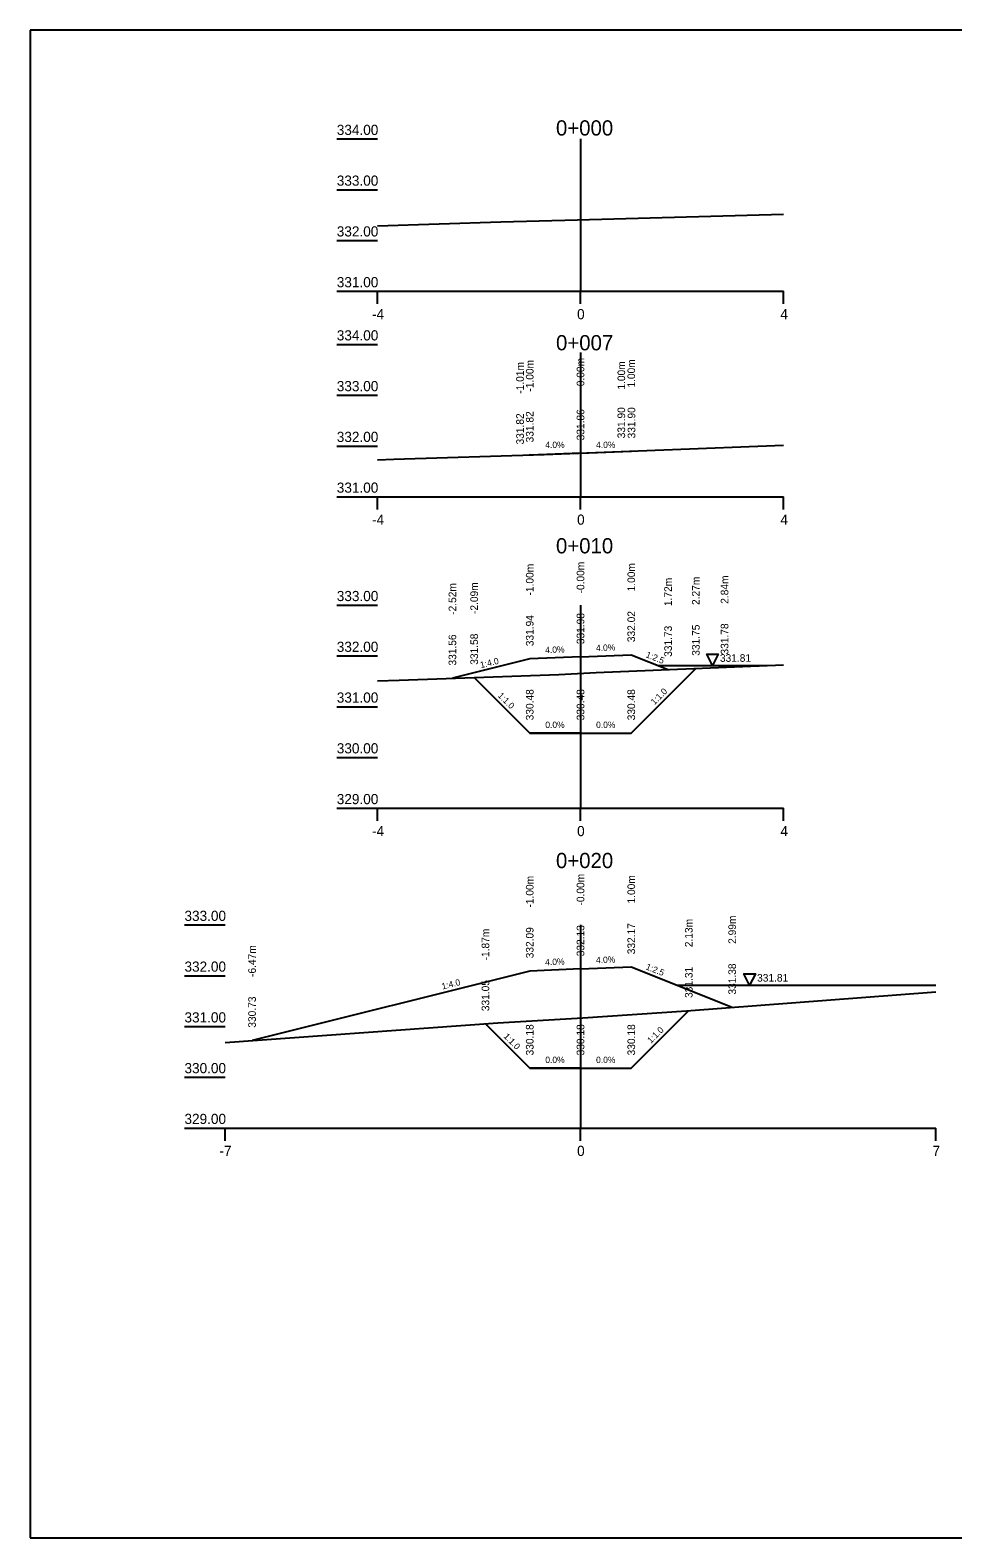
# Model space of a CAD drawing. Extents: x -560471.6 to -560429.6, y -1163651 to -1163621.3.
# Drawn here: x -560471.64 to -560453.47, y -1163650.97 to -1163621.27 of the extents above; entities that cross this region are included whole.
import ezdxf

# ---------------------------------------------------------------- set-up
doc = ezdxf.new("R2010")
doc.units = 0
for name, color, linetype in [('16', 7, 'Continuous'), ('21', 7, 'Continuous'), ('28', 7, 'Continuous'), ('59', 7, 'Continuous'), ('Body pricny rez', 7, 'Continuous'), ('Popis pricneho profilu', 7, 'Continuous')]:
    doc.layers.add(name, color=color, linetype=linetype)

msp = doc.modelspace()

# ---------------------------------------------------------------- linework, layer by layer
for p, q in [((-560429.645, -1163621.275), (-560471.645, -1163621.275)), ((-560471.645, -1163621.275), (-560471.645, -1163650.975)), ((-560471.645, -1163650.975), (-560429.645, -1163650.975))]:
    msp.add_line(p, q)
for points in [[(-560464.805, -1163625.129), (-560462.376, -1163625.054), (-560460.867, -1163625.01), (-560456.805, -1163624.899)], [(-560464.805, -1163629.74), (-560464.481, -1163629.729), (-560461.518, -1163629.633), (-560456.805, -1163629.453)], [(-560461.805, -1163629.646), (-560461.82, -1163629.643)], [(-560460.805, -1163629.606), (-560461.805, -1163629.646)], [(-560460.805, -1163629.606), (-560459.805, -1163629.566)], [(-560459.805, -1163629.566), (-560459.801, -1163629.567)], [(-560464.805, -1163634.095), (-560464.379, -1163634.08), (-560461.23, -1163633.965), (-560460.499, -1163633.93), (-560456.805, -1163633.777)], [(-560461.805, -1163633.661), (-560463.328, -1163634.042)], [(-560460.805, -1163633.621), (-560461.805, -1163633.661)], [(-560460.805, -1163633.621), (-560459.805, -1163633.581)], [(-560459.805, -1163633.581), (-560459.08, -1163633.871)], [(-560459.281, -1163633.791), (-560457.131, -1163633.791)], [(-560462.899, -1163634.026), (-560461.805, -1163635.121), (-560460.805, -1163635.121), (-560459.805, -1163635.121), (-560458.533, -1163633.849)], [(-560461.805, -1163635.121), (-560462.899, -1163634.026)], [(-560459.805, -1163635.121), (-560458.533, -1163633.849)], [(-560460.805, -1163635.121), (-560461.805, -1163635.121)], [(-560460.805, -1163635.121), (-560459.805, -1163635.121)], [(-560460.805, -1163639.769), (-560459.805, -1163639.729)], [(-560459.805, -1163639.729), (-560457.817, -1163640.524)], [(-560461.805, -1163639.809), (-560467.274, -1163641.176)], [(-560460.805, -1163639.769), (-560461.805, -1163639.809)], [(-560467.805, -1163641.214), (-560462.436, -1163640.833), (-560460.759, -1163640.733), (-560458.714, -1163640.593), (-560453.805, -1163640.216)], [(-560458.901, -1163640.091), (-560453.805, -1163640.091)], [(-560462.677, -1163640.85), (-560461.805, -1163641.722), (-560460.805, -1163641.722), (-560459.805, -1163641.722), (-560458.673, -1163640.59)], [(-560459.805, -1163641.722), (-560458.673, -1163640.59)], [(-560461.805, -1163641.722), (-560462.677, -1163640.85)], [(-560460.805, -1163641.722), (-560461.805, -1163641.722)], [(-560460.805, -1163641.722), (-560459.805, -1163641.722)]]:
    msp.add_lwpolyline(points)
for points in [[(-560458.206, -1163633.791), (-560458.319, -1163633.566), (-560458.094, -1163633.566)], [(-560457.474, -1163640.091), (-560457.586, -1163639.866), (-560457.361, -1163639.866)]]:
    msp.add_lwpolyline(points, close=True)
at = {"layer": '16'}
for p, q in [((-560464.805, -1163626.419), (-560456.805, -1163626.419)), ((-560464.805, -1163630.467), (-560456.805, -1163630.467)), ((-560464.805, -1163636.602), (-560456.805, -1163636.602)), ((-560467.805, -1163642.902), (-560453.805, -1163642.902))]:
    msp.add_line(p, q, dxfattribs=at)
at = {"layer": '21'}
for p, q in [((-560465.605, -1163623.419), (-560464.805, -1163623.419)), ((-560465.605, -1163624.419), (-560464.805, -1163624.419)), ((-560465.605, -1163625.419), (-560464.805, -1163625.419)), ((-560465.605, -1163626.419), (-560464.805, -1163626.419)), ((-560465.605, -1163627.467), (-560464.805, -1163627.467)), ((-560465.605, -1163628.467), (-560464.805, -1163628.467)), ((-560465.605, -1163629.467), (-560464.805, -1163629.467)), ((-560465.605, -1163630.467), (-560464.805, -1163630.467)), ((-560465.605, -1163632.602), (-560464.805, -1163632.602)), ((-560465.605, -1163633.602), (-560464.805, -1163633.602)), ((-560465.605, -1163634.602), (-560464.805, -1163634.602)), ((-560465.605, -1163635.602), (-560464.805, -1163635.602)), ((-560465.605, -1163636.602), (-560464.805, -1163636.602)), ((-560468.605, -1163638.902), (-560467.805, -1163638.902)), ((-560468.605, -1163639.902), (-560467.805, -1163639.902)), ((-560468.605, -1163640.902), (-560467.805, -1163640.902)), ((-560468.605, -1163641.902), (-560467.805, -1163641.902)), ((-560468.605, -1163642.902), (-560467.805, -1163642.902))]:
    msp.add_line(p, q, dxfattribs=at)
at = {"layer": '28'}
for p, q in [((-560460.805, -1163623.419), (-560460.805, -1163626.419)), ((-560460.805, -1163627.623), (-560460.805, -1163630.467)), ((-560460.805, -1163632.602), (-560460.805, -1163636.602)), ((-560460.805, -1163638.902), (-560460.805, -1163642.902))]:
    msp.add_line(p, q, dxfattribs=at)
at = {"layer": '59'}
for p, q in [((-560464.805, -1163626.669), (-560464.805, -1163626.419)), ((-560460.805, -1163626.669), (-560460.805, -1163626.419)), ((-560456.805, -1163626.669), (-560456.805, -1163626.419)), ((-560464.805, -1163630.717), (-560464.805, -1163630.467)), ((-560460.805, -1163630.717), (-560460.805, -1163630.467)), ((-560456.805, -1163630.717), (-560456.805, -1163630.467)), ((-560464.805, -1163636.852), (-560464.805, -1163636.602)), ((-560460.805, -1163636.852), (-560460.805, -1163636.602)), ((-560456.805, -1163636.852), (-560456.805, -1163636.602)), ((-560467.805, -1163643.152), (-560467.805, -1163642.902)), ((-560460.805, -1163643.152), (-560460.805, -1163642.902)), ((-560453.805, -1163643.152), (-560453.805, -1163642.902))]:
    msp.add_line(p, q, dxfattribs=at)

# ---------------------------------------------------------------- texts
for s, height, p in [('0+000', 0.3, (-560461.288, -1163623.351)), ('0+007', 0.3, (-560461.287, -1163627.582)), ('0+010', 0.3, (-560461.288, -1163631.582)), ('331.81', 0.15, (-560458.059, -1163633.718)), ('0+020', 0.3, (-560461.288, -1163637.782)), ('331.81', 0.15, (-560457.327, -1163640.018))]:
    msp.add_text(s, height=height).set_placement(p)
for s, rotation, p in [('1:2.5', 338.1986, (-560459.53, -1163633.624)), ('1:4.0', 14.0362, (-560462.765, -1163633.845)), ('1:1.0', 315, (-560462.442, -1163634.395)), ('1:1.0', 45, (-560459.347, -1163634.575)), ('1:2.5', 338.1986, (-560459.53, -1163639.772)), ('1:4.0', 14.0362, (-560463.523, -1163640.174)), ('1:1.0', 45, (-560459.417, -1163641.246)), ('1:1.0', 315, (-560462.331, -1163641.107))]:
    msp.add_text(s, height=0.125, rotation=rotation).set_placement(p)
at = {"layer": '16'}
for s, p in [('4.0%', (-560461.498, -1163629.506)), ('4.0%', (-560460.498, -1163629.506)), ('0.0%', (-560461.498, -1163635.021)), ('0.0%', (-560460.498, -1163635.021)), ('0.0%', (-560461.498, -1163641.622)), ('0.0%', (-560460.498, -1163641.622))]:
    msp.add_text(s, height=0.125, dxfattribs=at).set_placement(p)
for p in [(-560461.498, -1163633.549), (-560460.498, -1163633.509), (-560461.498, -1163639.697), (-560460.498, -1163639.657)]:
    msp.add_text('4.0%', height=0.125, rotation=2.2906, dxfattribs=at).set_placement(p)
at = {"layer": '21'}
for s, p in [('334.00', (-560465.605, -1163623.339)), ('333.00', (-560465.605, -1163624.339)), ('332.00', (-560465.605, -1163625.339)), ('331.00', (-560465.605, -1163626.339)), ('-4', (-560464.911, -1163626.969)), ('0', (-560460.872, -1163626.969)), ('4', (-560456.868, -1163626.969)), ('334.00', (-560465.605, -1163627.387)), ('333.00', (-560465.605, -1163628.387)), ('332.00', (-560465.605, -1163629.387)), ('331.00', (-560465.605, -1163630.387)), ('-4', (-560464.911, -1163631.017)), ('0', (-560460.872, -1163631.017)), ('4', (-560456.868, -1163631.017)), ('333.00', (-560465.605, -1163632.522)), ('332.00', (-560465.605, -1163633.522)), ('331.00', (-560465.605, -1163634.522)), ('330.00', (-560465.605, -1163635.522)), ('329.00', (-560465.605, -1163636.522)), ('-4', (-560464.911, -1163637.152)), ('0', (-560460.872, -1163637.152)), ('4', (-560456.868, -1163637.152)), ('333.00', (-560468.605, -1163638.822)), ('332.00', (-560468.605, -1163639.822)), ('331.00', (-560468.605, -1163640.822)), ('330.00', (-560468.605, -1163641.822)), ('329.00', (-560468.605, -1163642.822)), ('-7', (-560467.916, -1163643.452)), ('0', (-560460.872, -1163643.452)), ('7', (-560453.872, -1163643.452))]:
    msp.add_text(s, height=0.2, dxfattribs=at).set_placement(p)
at = {"layer": 'Body pricny rez'}
for p in [(-560461.82, -1163629.643), (-560461.805, -1163629.646), (-560460.805, -1163629.606), (-560460.805, -1163629.606), (-560459.805, -1163629.566), (-560459.801, -1163629.568), (-560457.103, -1163629.465), (-560461.805, -1163633.662), (-560460.805, -1163633.622), (-560459.805, -1163633.582), (-560463.329, -1163634.043), (-560462.9, -1163634.027), (-560459.08, -1163633.872), (-560458.533, -1163633.849), (-560457.968, -1163633.826), (-560461.805, -1163635.121), (-560460.805, -1163635.121), (-560459.805, -1163635.121), (-560459.805, -1163639.73), (-560461.805, -1163639.81), (-560460.805, -1163639.77), (-560458.673, -1163640.591), (-560457.817, -1163640.525), (-560462.678, -1163640.85), (-560467.274, -1163641.177), (-560461.805, -1163641.723), (-560460.805, -1163641.723), (-560459.805, -1163641.723)]:
    msp.add_text('+', height=0.001, dxfattribs=at).set_placement(p)
at = {"layer": 'Popis pricneho profilu'}
for s, p in [('-1.01m', (-560461.921, -1163628.437)), ('-1.00m', (-560461.73, -1163628.396)), ('-0.00m', (-560460.73, -1163628.356)), ('1.00m', (-560459.926, -1163628.356)), ('1.00m', (-560459.73, -1163628.316)), ('331.86', (-560460.73, -1163629.356)), ('331.90', (-560459.926, -1163629.316)), ('331.90', (-560459.726, -1163629.317)), ('331.82', (-560461.921, -1163629.437)), ('331.82', (-560461.73, -1163629.396)), ('-1.00m', (-560461.73, -1163632.411)), ('-0.00m', (-560460.73, -1163632.371)), ('1.00m', (-560459.73, -1163632.331)), ('2.84m', (-560457.892, -1163632.575)), ('-2.52m', (-560463.253, -1163632.792)), ('-2.09m', (-560462.824, -1163632.776)), ('1.72m', (-560459.005, -1163632.621)), ('2.27m', (-560458.458, -1163632.599)), ('331.94', (-560461.73, -1163633.411)), ('331.98', (-560460.73, -1163633.371)), ('332.02', (-560459.73, -1163633.331)), ('331.56', (-560463.253, -1163633.792)), ('331.58', (-560462.824, -1163633.776)), ('331.73', (-560459.005, -1163633.621)), ('331.75', (-560458.458, -1163633.599)), ('331.78', (-560457.892, -1163633.575)), ('330.48', (-560461.73, -1163634.871)), ('330.48', (-560460.73, -1163634.871)), ('330.48', (-560459.73, -1163634.871)), ('-1.00m', (-560461.73, -1163638.559)), ('-0.00m', (-560460.73, -1163638.519)), ('1.00m', (-560459.73, -1163638.479)), ('2.13m', (-560458.598, -1163639.34)), ('2.99m', (-560457.742, -1163639.274)), ('-1.87m', (-560462.602, -1163639.6)), ('332.09', (-560461.73, -1163639.559)), ('332.13', (-560460.73, -1163639.519)), ('332.17', (-560459.73, -1163639.479)), ('-6.47m', (-560467.199, -1163639.926)), ('331.31', (-560458.598, -1163640.34)), ('331.38', (-560457.742, -1163640.274)), ('331.05', (-560462.602, -1163640.6)), ('330.73', (-560467.199, -1163640.926)), ('330.18', (-560461.73, -1163641.472)), ('330.18', (-560460.73, -1163641.472)), ('330.18', (-560459.73, -1163641.472))]:
    msp.add_text(s, height=0.15, rotation=90, dxfattribs=at).set_placement(p)

doc.saveas('drawing.dxf')
